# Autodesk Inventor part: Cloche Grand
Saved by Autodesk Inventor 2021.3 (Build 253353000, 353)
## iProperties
Created: 2022-06
Part Number: Cloche Grand
Material: Generic
Document SubType Name: Modeling
Designer: Administrator
Density: 1 g/cm^3
Appearance: Default
Title: Cloche Grand v2
Author: Administrator
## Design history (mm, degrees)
feature "Body1"
feature "Socket Body" [Body]
feature "Shade Ring" [Body]
feature "Shade Ring +Collar" [Body]
feature "Socket" [Body]
feature "Body1 (1)"
feature "Metal Strain Relief" [Body]
feature "Fabric Cord (1)" [Body]
feature "Stem (Threaded)" [Body]
feature "Cap (Threaded)" [Body]
feature "5M Set Screw" [Body]
feature "T8-Bulb" [Body]
body "Solid1"
body "Solid2"
body "Solid3"
body "Solid4"
body "Solid5"
body "Solid6"
body "Solid7"
body "Solid8"
body "Solid9"
body "Solid10"
body "Solid11"
body "Solid12"
